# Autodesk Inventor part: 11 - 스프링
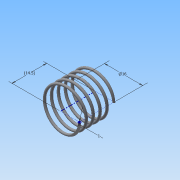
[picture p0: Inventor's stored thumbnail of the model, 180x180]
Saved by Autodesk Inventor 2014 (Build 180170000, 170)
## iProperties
Created: 2015-06
Part Number: 11 - 스프링
Material: 강철, 연강
Document SubType Name: Modeling
Designer: Administrator
Density: 7.86 g/cm^3
Appearance: 강철
Mass: 1.52988 g
Surface Area: 7.87024 cm^2
Volume: 0.194641 cm^3
Author: Administrator
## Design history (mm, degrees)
sketch "스케치1"
  geometry: L1 (0, 0)-(8, 0); L2 (8, 0)-(8, 14.5); L3 (8, 14.5)-(0, 14.5); L4 (0, 14.5)-(0, 0); C1 r 0.5 at (8, 0)
  constraints: 8 end point, 2 parallel, 1 centre point, 1 coincident, 1 horizontal, 1 perpendicular
  dimensions: "d0" = 14.5 distance between parallel lines of L1 L3 (derived); "d1" = 16 diameter of L2 L4; "d2" = 1 diameter of C1
feature "코일1" sketch "스케치1" pitch "d3" = 10; turns "d5" = 5; dims "d4" = 14.5 (= d0), "d6" = 0, angle "d7" = 90 deg, angle "d8" = 90 deg, "d9" = 0, "d10" = 0
node "작업 평면1"
sketch "스케치2"
  geometry: L1 (-8.5, 0)-(-7.5, 0) reference; 1 further point
  constraints: 1 horizontal alignment
extrude "돌출1" cut sketch "스케치2" distance "d12" = 10; taper "d13" = 0 deg
node "작업 평면2"
sketch "스케치3"
  geometry: L1 (-7.5, 0)-(-8.5, 0) reference; 1 further point
  constraints: 1 horizontal alignment
extrude "돌출2" cut sketch "스케치3" stored distance "d15" = 10; taper "d16" = 0 deg
node "솔리드1"
node "절단 모서리 투영1"
node "절단 모서리 투영2"
other parameters: "d11" = 0, "d14" = 14.5 (= d0)
